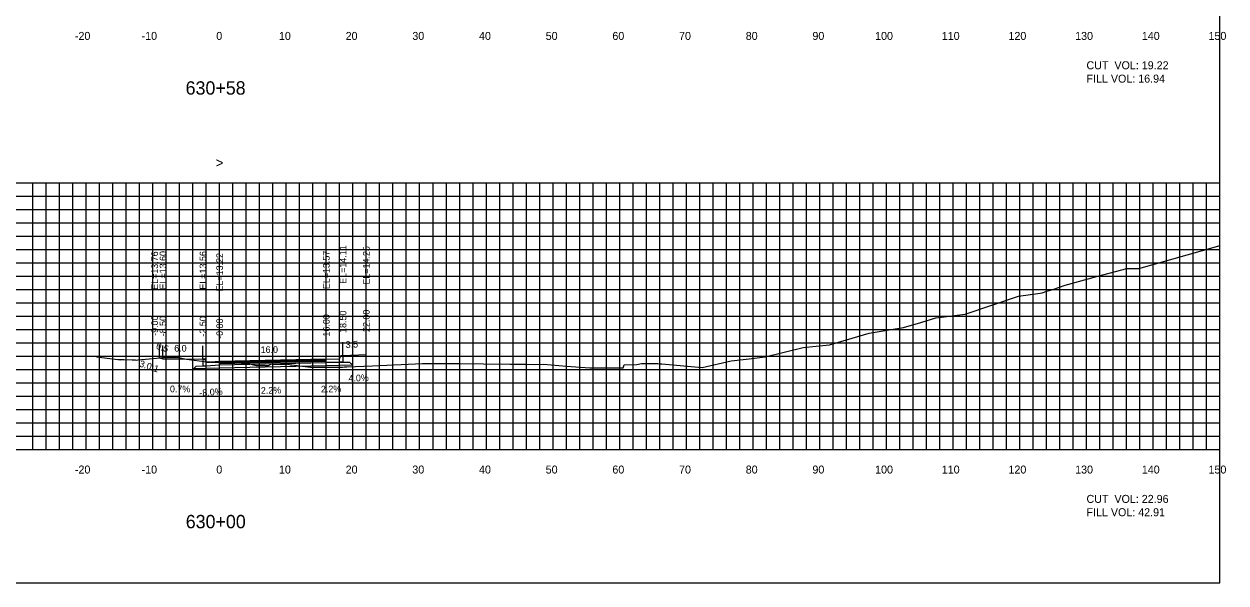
# Model space of a CAD drawing. Extents: x 1797645 to 1803805, y 248417 to 250269.
# Drawn here: x 1803281.7 to 1803461.9, y 250079.4 to 250163.2 of the extents above; entities that cross this region are included whole.
import ezdxf

# ---------------------------------------------------------------- set-up
doc = ezdxf.new("R2010")
doc.units = 0
for name, color, linetype in [('1', 7, 'Continuous'), ('10', 7, 'Continuous'), ('3', 7, 'Continuous'), ('4', 7, 'Continuous'), ('60', 7, 'Continuous'), ('ANNO-TXT', 7, 'Continuous'), ('BASE', 7, 'Continuous'), ('CL-CNST', 7, 'Continuous'), ('Level 62', 7, 'Continuous'), ('LOWER BINDER', 7, 'Continuous'), ('M-ROADS', 7, 'Continuous'), ('UPPER BINDER', 7, 'Continuous'), ('WEARING', 7, 'Continuous')]:
    doc.layers.add(name, color=color, linetype=linetype)

msp = doc.modelspace()

# ---------------------------------------------------------------- linework, layer by layer
for p, q in [((1803333, 250113.68), (1803333, 250115.68)), ((1803302, 250113.19), (1803302, 250115.19)), ((1803302.5, 250113.03), (1803302.5, 250115.03)), ((1803308.5, 250112.99), (1803308.5, 250114.99)), ((1803308.5, 250112.99), (1803308.5, 250114.99)), ((1803311, 250112.65), (1803311, 250114.65)), ((1803327, 250113), (1803327, 250115)), ((1803329.5, 250113.54), (1803329.5, 250115.54))]:
    msp.add_line(p, q)
for points in [[(1803161, 250079.43), (1803461, 250079.43), (1803461, 250269.43), (1803161, 250269.43)], [(1803311, 250112.65), (1803309, 250112.49), (1803308.83, 250112.99), (1803308.5, 250112.99), (1803308.5, 250111.96), (1803309, 250111.96), (1803311, 250112.12)], [(1803327, 250113), (1803329, 250113.04), (1803329.17, 250113.54), (1803329.5, 250113.54), (1803329.5, 250112.51), (1803329, 250112.51), (1803327, 250112.47)]]:
    msp.add_lwpolyline(points, close=True)
at = {"layer": '60'}
for p, q in [((1803461, 250099.43), (1803461, 250139.43)), ((1803461.06, 250139.43), (1803461, 250139.43)), ((1803461.06, 250129.43), (1803461, 250129.43)), ((1803461.06, 250119.43), (1803461, 250119.43)), ((1803461.06, 250109.43), (1803461, 250109.43)), ((1803161, 250099.43), (1803461, 250099.43)), ((1803291, 250099.37), (1803291, 250099.43)), ((1803301, 250099.37), (1803301, 250099.43)), ((1803311, 250099.37), (1803311, 250099.43)), ((1803321, 250099.37), (1803321, 250099.43)), ((1803331, 250099.37), (1803331, 250099.43)), ((1803341, 250099.37), (1803341, 250099.43)), ((1803351, 250099.37), (1803351, 250099.43)), ((1803361, 250099.37), (1803361, 250099.43)), ((1803371, 250099.37), (1803371, 250099.43)), ((1803381, 250099.37), (1803381, 250099.43)), ((1803391, 250099.37), (1803391, 250099.43)), ((1803401, 250099.37), (1803401, 250099.43)), ((1803411, 250099.37), (1803411, 250099.43)), ((1803421, 250099.37), (1803421, 250099.43)), ((1803431, 250099.37), (1803431, 250099.43)), ((1803441, 250099.37), (1803441, 250099.43)), ((1803451, 250099.37), (1803451, 250099.43)), ((1803461, 250099.37), (1803461, 250099.43)), ((1803461.06, 250099.43), (1803461, 250099.43))]:
    msp.add_line(p, q, dxfattribs=at)
at = {"layer": 'BASE'}
msp.add_lwpolyline([(1803311, 250112.12), (1803327, 250112.47), (1803329, 250112.51), (1803329.5, 250112.51), (1803330.5, 250112.54), (1803330.98, 250112.06), (1803327, 250111.97), (1803311, 250111.62), (1803307.09, 250111.53), (1803307.5, 250111.94), (1803308.5, 250111.96), (1803309, 250111.96)], close=True, dxfattribs=at)
at = {"layer": 'CL-CNST'}
msp.add_lwpolyline([(1803302, 250113.19), (1803302.5, 250113.03), (1803308.5, 250112.99), (1803308.5, 250112.99), (1803308.83, 250112.99), (1803309, 250112.49), (1803311, 250112.65), (1803327, 250113), (1803329, 250113.04), (1803329.17, 250113.54), (1803329.5, 250113.54), (1803333, 250113.68)], dxfattribs=at)
at = {"layer": 'Level 62'}
for p, q in [((1803161, 250139.43), (1803461, 250139.43)), ((1803283, 250099.43), (1803283, 250139.43)), ((1803285, 250099.43), (1803285, 250139.43)), ((1803287, 250099.43), (1803287, 250139.43)), ((1803289, 250099.43), (1803289, 250139.43)), ((1803291, 250099.43), (1803291, 250139.43)), ((1803293, 250099.43), (1803293, 250139.43)), ((1803295, 250099.43), (1803295, 250139.43)), ((1803297, 250099.43), (1803297, 250139.43)), ((1803299, 250099.43), (1803299, 250139.43)), ((1803301, 250099.43), (1803301, 250139.43)), ((1803303, 250099.43), (1803303, 250139.43)), ((1803305, 250099.43), (1803305, 250139.43)), ((1803307, 250099.43), (1803307, 250139.43)), ((1803309, 250099.43), (1803309, 250139.43)), ((1803311, 250099.43), (1803311, 250139.43)), ((1803313, 250099.43), (1803313, 250139.43)), ((1803315, 250099.43), (1803315, 250139.43)), ((1803317, 250099.43), (1803317, 250139.43)), ((1803319, 250099.43), (1803319, 250139.43)), ((1803321, 250099.43), (1803321, 250139.43)), ((1803323, 250099.43), (1803323, 250139.43)), ((1803325, 250099.43), (1803325, 250139.43)), ((1803327, 250099.43), (1803327, 250139.43)), ((1803329, 250099.43), (1803329, 250139.43)), ((1803331, 250099.43), (1803331, 250139.43)), ((1803333, 250099.43), (1803333, 250139.43)), ((1803335, 250099.43), (1803335, 250139.43)), ((1803337, 250099.43), (1803337, 250139.43)), ((1803339, 250099.43), (1803339, 250139.43)), ((1803341, 250099.43), (1803341, 250139.43)), ((1803343, 250099.43), (1803343, 250139.43)), ((1803345, 250099.43), (1803345, 250139.43)), ((1803347, 250099.43), (1803347, 250139.43)), ((1803349, 250099.43), (1803349, 250139.43)), ((1803351, 250099.43), (1803351, 250139.43)), ((1803353, 250099.43), (1803353, 250139.43)), ((1803355, 250099.43), (1803355, 250139.43)), ((1803357, 250099.43), (1803357, 250139.43)), ((1803359, 250099.43), (1803359, 250139.43)), ((1803361, 250099.43), (1803361, 250139.43)), ((1803363, 250099.43), (1803363, 250139.43)), ((1803365, 250099.43), (1803365, 250139.43)), ((1803367, 250099.43), (1803367, 250139.43)), ((1803369, 250099.43), (1803369, 250139.43)), ((1803371, 250099.43), (1803371, 250139.43)), ((1803373, 250099.43), (1803373, 250139.43)), ((1803375, 250099.43), (1803375, 250139.43)), ((1803377, 250099.43), (1803377, 250139.43)), ((1803379, 250099.43), (1803379, 250139.43)), ((1803381, 250099.43), (1803381, 250139.43)), ((1803383, 250099.43), (1803383, 250139.43)), ((1803385, 250099.43), (1803385, 250139.43)), ((1803387, 250099.43), (1803387, 250139.43)), ((1803389, 250099.43), (1803389, 250139.43)), ((1803391, 250099.43), (1803391, 250139.43)), ((1803393, 250099.43), (1803393, 250139.43)), ((1803395, 250099.43), (1803395, 250139.43)), ((1803397, 250099.43), (1803397, 250139.43)), ((1803399, 250099.43), (1803399, 250139.43)), ((1803401, 250099.43), (1803401, 250139.43)), ((1803403, 250099.43), (1803403, 250139.43)), ((1803405, 250099.43), (1803405, 250139.43)), ((1803407, 250099.43), (1803407, 250139.43)), ((1803409, 250099.43), (1803409, 250139.43)), ((1803411, 250099.43), (1803411, 250139.43)), ((1803413, 250099.43), (1803413, 250139.43)), ((1803415, 250099.43), (1803415, 250139.43)), ((1803417, 250099.43), (1803417, 250139.43)), ((1803419, 250099.43), (1803419, 250139.43)), ((1803421, 250099.43), (1803421, 250139.43)), ((1803423, 250099.43), (1803423, 250139.43)), ((1803425, 250099.43), (1803425, 250139.43)), ((1803427, 250099.43), (1803427, 250139.43)), ((1803429, 250099.43), (1803429, 250139.43)), ((1803431, 250099.43), (1803431, 250139.43)), ((1803433, 250099.43), (1803433, 250139.43)), ((1803435, 250099.43), (1803435, 250139.43)), ((1803437, 250099.43), (1803437, 250139.43)), ((1803439, 250099.43), (1803439, 250139.43)), ((1803441, 250099.43), (1803441, 250139.43)), ((1803443, 250099.43), (1803443, 250139.43)), ((1803445, 250099.43), (1803445, 250139.43)), ((1803447, 250099.43), (1803447, 250139.43)), ((1803449, 250099.43), (1803449, 250139.43)), ((1803451, 250099.43), (1803451, 250139.43)), ((1803453, 250099.43), (1803453, 250139.43)), ((1803455, 250099.43), (1803455, 250139.43)), ((1803457, 250099.43), (1803457, 250139.43)), ((1803459, 250099.43), (1803459, 250139.43)), ((1803461, 250099.43), (1803461, 250139.43)), ((1803161, 250137.43), (1803461, 250137.43)), ((1803161, 250135.43), (1803461, 250135.43)), ((1803161, 250133.43), (1803461, 250133.43)), ((1803161, 250131.43), (1803461, 250131.43)), ((1803161, 250129.43), (1803461, 250129.43)), ((1803161, 250127.43), (1803461, 250127.43)), ((1803161, 250125.43), (1803461, 250125.43)), ((1803161, 250123.43), (1803461, 250123.43)), ((1803161, 250121.43), (1803461, 250121.43)), ((1803161, 250119.43), (1803461, 250119.43)), ((1803161, 250117.43), (1803461, 250117.43)), ((1803161, 250115.43), (1803461, 250115.43)), ((1803161, 250113.43), (1803461, 250113.43)), ((1803161, 250111.43), (1803461, 250111.43)), ((1803161, 250109.43), (1803461, 250109.43)), ((1803161, 250107.43), (1803461, 250107.43)), ((1803161, 250105.43), (1803461, 250105.43)), ((1803161, 250103.43), (1803461, 250103.43)), ((1803161, 250101.43), (1803461, 250101.43)), ((1803161, 250099.43), (1803461, 250099.43))]:
    msp.add_line(p, q, dxfattribs=at)
at = {"layer": 'LOWER BINDER'}
msp.add_lwpolyline([(1803327, 250112.47), (1803327, 250112.47), (1803327, 250112.66), (1803311, 250112.31), (1803311, 250112.12)], close=True, dxfattribs=at)
at = {"layer": 'M-ROADS'}
msp.add_lwpolyline([(1803292.56, 250113.35), (1803295.72, 250112.93), (1803296.1, 250112.94), (1803296.17, 250112.9), (1803296.18, 250112.93), (1803296.65, 250112.93), (1803297.89, 250112.87), (1803298.36, 250112.87), (1803298.49, 250112.84), (1803298.73, 250112.86), (1803301.59, 250113.15), (1803302.53, 250113.25), (1803303.74, 250113.25), (1803304.84, 250113.25), (1803306.03, 250112.97), (1803309.1, 250112.56), (1803309.51, 250112.56), (1803309.75, 250112.52), (1803312.18, 250112.42), (1803312.56, 250112.37), (1803313.59, 250112.42), (1803314.88, 250112.33), (1803315.15, 250112.36), (1803316.49, 250112.05), (1803318.22, 250112.02), (1803318.35, 250112.05), (1803318.8, 250112.28), (1803319.08, 250112.24), (1803321.06, 250112.22), (1803321.13, 250112.18), (1803321.16, 250112.22), (1803321.17, 250112.21), (1803321.18, 250112.22), (1803321.29, 250112.22), (1803321.64, 250112.15), (1803321.82, 250112.13), (1803322.24, 250112.08), (1803324.24, 250111.82), (1803324.39, 250111.82), (1803324.62, 250111.8), (1803325.54, 250111.8), (1803326.92, 250111.8), (1803328.67, 250111.8), (1803329.41, 250111.8), (1803329.68, 250111.82), (1803330.06, 250111.83), (1803333.94, 250111.98), (1803341.43, 250112.31), (1803341.99, 250112.34), (1803343.26, 250112.32), (1803344.51, 250112.33), (1803344.7, 250112.33), (1803346.99, 250112.33), (1803350.56, 250112.28), (1803354.58, 250112.21), (1803356.73, 250112.21), (1803357.08, 250112.21), (1803358.27, 250112.2), (1803359.59, 250112.21), (1803363.02, 250111.94), (1803366.5, 250111.69), (1803367.79, 250111.7), (1803369.02, 250111.68), (1803369.15, 250111.67), (1803371.23, 250111.66), (1803371.5, 250111.7), (1803371.69, 250112.14), (1803373.57, 250112.17), (1803374.27, 250112.33), (1803376.41, 250112.33), (1803376.71, 250112.34), (1803377, 250112.3), (1803377.33, 250112.29), (1803383.37, 250111.75), (1803387.71, 250112.71), (1803390.4, 250113.04), (1803392.81, 250113.34), (1803398.51, 250114.75), (1803400.45, 250114.93), (1803402.46, 250115.11), (1803408.43, 250116.88), (1803411.4, 250117.38), (1803413.56, 250117.73), (1803416.16, 250118.49), (1803418.4, 250119.19), (1803419.66, 250119.33), (1803422.81, 250119.7), (1803430.81, 250122.42), (1803434.04, 250122.87), (1803434.34, 250122.91), (1803435.06, 250123.15), (1803435.96, 250123.4), (1803437.78, 250124.07), (1803442.71, 250125.4), (1803447.03, 250126.57), (1803447.98, 250126.57), (1803448.84, 250126.57), (1803460.7, 250129.92), (1803461, 250130.03)], dxfattribs=at)
at = {"layer": 'UPPER BINDER'}
msp.add_lwpolyline([(1803327, 250112.66), (1803327, 250112.85), (1803311, 250112.5), (1803311, 250112.31)], close=True, dxfattribs=at)
at = {"layer": 'WEARING'}
msp.add_lwpolyline([(1803327, 250112.85), (1803327, 250113), (1803311, 250112.65), (1803311, 250112.5)], close=True, dxfattribs=at)

# ---------------------------------------------------------------- texts
msp.add_text('3.0:1', height=1, rotation=341.5651).set_placement((1803298.87, 250111.91))
at = {"layer": '1'}
for s, p in [('630+58', (1803305.9, 250152.63)), ('630+00', (1803305.92, 250087.63))]:
    msp.add_text(s, height=2, dxfattribs=at).set_placement(p)
at = {"layer": '10'}
for s, p in [('-20', (1803289.3, 250160.83)), ('-10', (1803299.3, 250160.83)), ('0', (1803310.5, 250160.83)), ('10', (1803319.9, 250160.83)), ('20', (1803329.9, 250160.83)), ('30', (1803339.9, 250160.83)), ('40', (1803349.9, 250160.83)), ('50', (1803359.9, 250160.83)), ('60', (1803369.9, 250160.83)), ('70', (1803379.9, 250160.83)), ('80', (1803389.9, 250160.83)), ('90', (1803399.9, 250160.83)), ('100', (1803409.3, 250160.83)), ('110', (1803419.3, 250160.83)), ('120', (1803429.3, 250160.83)), ('130', (1803439.3, 250160.83)), ('140', (1803449.3, 250160.83)), ('150', (1803459.3, 250160.83)), ('-20', (1803289.3, 250095.83)), ('-10', (1803299.3, 250095.83)), ('0', (1803310.5, 250095.83)), ('10', (1803319.9, 250095.83)), ('20', (1803329.9, 250095.83)), ('30', (1803339.9, 250095.83)), ('40', (1803349.9, 250095.83)), ('50', (1803359.9, 250095.83)), ('60', (1803369.9, 250095.83)), ('70', (1803379.9, 250095.83)), ('80', (1803389.9, 250095.83)), ('90', (1803399.9, 250095.83)), ('100', (1803409.3, 250095.83)), ('110', (1803419.3, 250095.83)), ('120', (1803429.3, 250095.83)), ('130', (1803439.3, 250095.83)), ('140', (1803449.3, 250095.83)), ('150', (1803459.3, 250095.83))]:
    msp.add_text(s, height=1.2, dxfattribs=at).set_placement(p)
at = {"layer": '3'}
for s, p in [('EL=13.76', (1803301.76, 250123.37)), ('EL=13.60', (1803303, 250123.42)), ('EL=13.56', (1803309, 250123.41)), ('EL=13.56', (1803309, 250123.41)), ('EL=13.22', (1803311.5, 250123.12)), ('EL=13.57', (1803327.5, 250123.47)), ('EL=14.11', (1803330, 250124.27)), ('EL=14.25', (1803333.5, 250124.16)), ('-9.00', (1803301.76, 250116.47)), ('-8.50', (1803303, 250116.4)), ('-2.50', (1803309, 250116.36)), ('-2.50', (1803309, 250116.36)), ('16.00', (1803327.5, 250116.37)), ('18.50', (1803330, 250116.91)), ('22.00', (1803333.5, 250117.05)), ('-0.00', (1803311.5, 250116.02))]:
    msp.add_text(s, height=1, rotation=90, dxfattribs=at).set_placement(p)
at = {"layer": '4'}
for s, rotation, p in [('3.5', 2.2906, (1803329.92, 250114.66)), ('0.5', 341.5651, (1803301.38, 250114.56)), ('6.0', 359.6114, (1803304.19, 250114.12)), ('16.0', 1.2603, (1803317.16, 250113.88)), ('4.0%', 2.2906, (1803330.34, 250109.6)), ('0.7%', 359.6114, (1803303.55, 250108.02)), ('-8.0%', 4.5739, (1803308, 250107.39)), ('2.2%', 1.2603, (1803317.2, 250107.78)), ('2.2%', 1.2603, (1803326.2, 250107.98))]:
    msp.add_text(s, height=1, rotation=rotation, dxfattribs=at).set_placement(p)
at = {"layer": '60'}
msp.add_text('>', height=1.5, dxfattribs=at).set_placement((1803310.39, 250141.68))
at = {"layer": 'ANNO-TXT'}
for s, p in [('CUT  VOL: 19.22', (1803441, 250156.43)), ('FILL VOL: 16.94', (1803441, 250154.43)), ('CUT  VOL: 22.96', (1803441, 250091.43)), ('FILL VOL: 42.91', (1803441, 250089.43))]:
    msp.add_text(s, height=1.2, dxfattribs=at).set_placement(p)

doc.saveas('drawing.dxf')
